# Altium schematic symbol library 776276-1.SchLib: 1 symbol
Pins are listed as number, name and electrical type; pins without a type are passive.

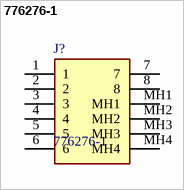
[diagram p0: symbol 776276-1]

## 776276-1
designator J?
8POS,PIN DIA 1.3,HDR ASSY,180DEG,SLDR,AMPSEAL, Automotive Headers, Wire-to-Board / Wire-to-Device, 8 Position, 4mm [.157in] Centerline, Sealable, Vertical, 3 Row, Black; Manufacturer_Name: TE Connectivity; Geometry.Height: 34.5mm
footprint 7762761
pins: 1, 2, 3, 4, 5, 6, 7, 8, MH1, MH2, MH3, MH4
